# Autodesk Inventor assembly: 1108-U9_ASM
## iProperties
Created: 2007-03
Part Number: 1108-U9_ASM
Document SubType Name: Assembly
Designer: Andy Moles
Mass: 22.4388 g
Surface Area: 73.9212 cm^2
Volume: 4.83188 cm^3
Density: 4.6439 g/cm^3
Author: Andy Moles
